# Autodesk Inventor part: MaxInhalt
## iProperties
Created: 2005-10
Part Number: MaxInhalt
Material: Milch
Document SubType Name: Modeling
Designer: rsc
Manufacturer: Standard
Standards Organization: Custom
Kanten: brechen
Oberflächen: Ra 3,2
Radien: 2
Toleranzen: ISO 2768 - m
Author: rsc
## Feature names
1. Hauptvolumen [Extrusion]
2. Leitung [Extrusion]
